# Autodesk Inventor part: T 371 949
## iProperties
Created: 2006-08
Part Number: T 371 949
Document SubType Name: Modeling
Designer: I.Baliuc
Description: Konfektioniertes Kabel
Density: 1 g/cm^3
Mass: 8.72057 g
Surface Area: 65.0891 cm^2
Volume: 8.72057 cm^3
Abmessung: L = 170 mm
Author: T.Messerschmitt
Revision Number: 371949
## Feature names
1. Basis1
